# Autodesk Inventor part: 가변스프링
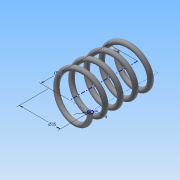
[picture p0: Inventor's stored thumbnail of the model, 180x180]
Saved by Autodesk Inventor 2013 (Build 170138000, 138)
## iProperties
Created: 2015-03
Part Number: 가변스프링
Material: 강철, 탄소
Document SubType Name: Modeling
Designer: Administrator
Density: 7.87 g/cm^3
Mass: 48.2733 g
Surface Area: 62.0009 cm^2
Volume: 6.13383 cm^3
Author: Administrator
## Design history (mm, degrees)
sketch "스케치1"
  geometry: L1 (0, 0)-(17.5, 0); L2 (17.5, 0)-(17.5, 43.5); L3 (17.5, 43.5)-(0, 43.5); L4 (0, 43.5)-(0, 0); C1 r 2 at (17.5, 0)
  constraints: 8 end point, 2 parallel, 1 centre point, 1 coincident, 1 horizontal, 1 perpendicular
  dimensions: "d0" = 43.5 distance of L3.end L1.start (derived); "d1" = 35 diameter of L2 L4; "d2" = 4 diameter of C1
feature "코일1" sketch "스케치1" pitch "d3" = 10; turns "d5" = 4.5; dims "d4" = 43.5 (= d0), "d6" = 0, angle "d7" = 90 deg, angle "d8" = 90 deg, "d9" = 0, "d10" = 0
sketch "스케치2"
  geometry: L1 (-19.5, 0)-(-15.5, 0) reference; 1 further point
  constraints: 1 horizontal alignment
extrude "돌출1" cut sketch "스케치2" stored distance "d11" = 10; taper "d12" = 0 deg
node "작업 평면1"
sketch "스케치3"
  geometry: L1 (-19.5, 0)-(-15.5, 0) reference; 1 further point
  constraints: 1 horizontal alignment
extrude "돌출2" cut sketch "스케치3" stored distance "d14" = 10; taper "d15" = 0 deg
node "솔리드1"
node "절단 모서리 투영1"
node "절단 모서리 투영2"
other parameters: "d13" = -43.5 (= -d0)
